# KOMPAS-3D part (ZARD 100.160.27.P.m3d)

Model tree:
1. Операция без истории:1
2. Операция без истории:2
3. Операция без истории:3
4. Операция без истории:4
5. Операция без истории:5
6. Операция без истории:6
7. Операция без истории:7
8. Операция без истории:8
9. Операция без истории:9
10. Операция без истории:10
11. Операция без истории:11
12. Операция без истории:12
13. Операция без истории:13
14. Операция без истории:14
15. Операция без истории:15
16. Операция без истории:16
17. Операция без истории:17
18. Операция без истории:18
19. Операция без истории:19
20. Операция без истории:20
21. Операция без истории:21
22. Операция без истории:22
23. Операция без истории:23
24. Операция без истории:24
25. Операция без истории:25
26. Операция без истории:26
27. Операция без истории:27
28. Операция без истории:28
29. Операция без истории:29
30. Операция без истории:30
31. Операция без истории:31
32. Операция без истории:32
33. Операция без истории:33
34. Операция без истории:34
35. Операция без истории:35
36. Операция без истории:36
37. Операция без истории:37
38. Операция без истории:38
39. Операция без истории:39
40. Операция без истории:40
41. Операция без истории:41
42. Операция без истории:42
43. Операция без истории:43
44. Операция без истории:44
45. Операция без истории:45
46. Операция без истории:46
47. Операция без истории:47
48. Операция без истории:48
49. Операция без истории:49
50. Операция без истории:50
51. Операция без истории:51
52. Операция без истории:52
53. Операция без истории:53
54. Операция без истории:54
55. Операция без истории:55
56. Операция без истории:56
57. Операция без истории:57
58. Операция без истории:58
59. Операция без истории:59
60. Операция без истории:60
61. Операция без истории:61
62. Операция без истории:62
63. Операция без истории:63
64. Операция без истории:64
65. Операция без истории:65
66. Операция без истории:66
67. Операция без истории:67
68. Операция без истории:68
69. Операция без истории:69
70. Операция без истории:70
71. Операция без истории:71
72. Операция без истории:72
73. Операция без истории:73
74. Операция без истории:74
75. Операция без истории:75
76. Операция без истории:76
77. Операция без истории:77
78. Операция без истории:78
79. Операция без истории:79
80. Операция без истории:80
81. Операция без истории:81
82. Операция без истории:82
83. Операция без истории:83
84. Операция без истории:84
85. Операция без истории:85
86. Операция без истории:86
87. Операция без истории:87
88. Поверхность без истории:1
89. Поверхность без истории:2
90. Поверхность без истории:3
91. Поверхность без истории:4
92. Поверхность без истории:5
93. Поверхность без истории:6
94. Поверхность без истории:7
95. Поверхность без истории:8

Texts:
  ЗАРД 100.160.27-ХХ.Р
